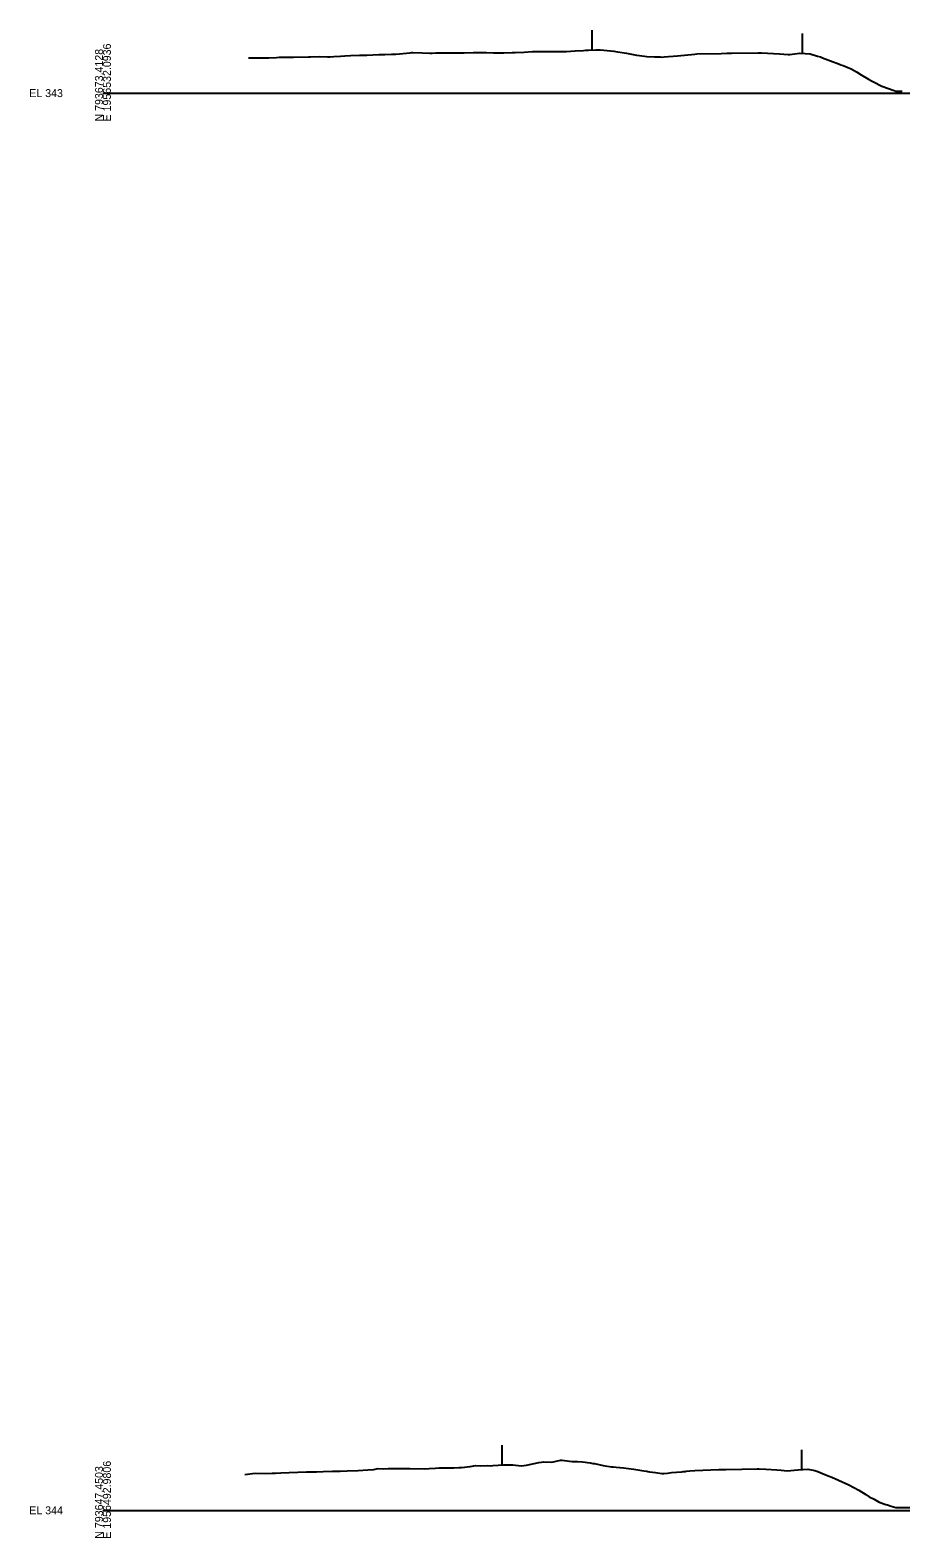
# Model space of a CAD drawing. Extents: x -4026 to 9638, y -10 to 19609.
# Drawn here: x -3026 to -2718, y -10 to 522 of the extents above; entities that cross this region are included whole.
import ezdxf

# ---------------------------------------------------------------- set-up
doc = ezdxf.new("R2010")
doc.units = 0
for name, color, linetype in [('Default', 7, 'Continuous'), ('RD_EX_Fence_Other', 7, 'Continuous'), ('RD_GPK_XS_Cell', 7, 'Continuous'), ('RD_XS_ExGround', 7, 'Continuous')]:
    doc.layers.add(name, color=color, linetype=linetype)

msp = doc.modelspace()

# ---------------------------------------------------------------- linework, layer by layer
at = {"layer": 'RD_EX_Fence_Other'}
for p, q in [((-2827.49, 522.22), (-2827.49, 515.22)), ((-2753.34, 521.04), (-2753.34, 514.04)), ((-2859.28, 23.03), (-2859.28, 16.03)), ((-2753.49, 21.41), (-2753.49, 14.41))]:
    msp.add_line(p, q, dxfattribs=at)
at = {"layer": 'RD_GPK_XS_Cell'}
for p, q in [((-3000, 500), (-2650, 500)), ((-3000, 0), (-2650, 0))]:
    msp.add_line(p, q, dxfattribs=at)
at = {"layer": 'RD_XS_ExGround'}
for points in [[(-2948.67, 512.41), (-2945.47, 512.47), (-2944.79, 512.47), (-2941.46, 512.47), (-2938.77, 512.62), (-2937.86, 512.66), (-2936.49, 512.71), (-2932.76, 512.74), (-2927.5, 512.78), (-2927.04, 512.8), (-2926.74, 512.8), (-2923.44, 512.9), (-2920.72, 512.84), (-2919.84, 512.84), (-2918.52, 512.9), (-2916.23, 513.05), (-2914.7, 513.13), (-2912.63, 513.28), (-2909.54, 513.37), (-2909.02, 513.4), (-2908.68, 513.4), (-2906.94, 513.45), (-2902.66, 513.57), (-2900.56, 513.62), (-2898.21, 513.73), (-2896.64, 513.8), (-2891.58, 514.23), (-2891.01, 514.3), (-2890.62, 514.29), (-2887.4, 514.16), (-2884.61, 514.15), (-2883.8, 514.14), (-2882.59, 514.17), (-2880.19, 514.22), (-2878.59, 514.25), (-2873.61, 514.26), (-2872.57, 514.27), (-2869.38, 514.37), (-2866.55, 514.33), (-2865.78, 514.32), (-2864.63, 514.32), (-2862.17, 514.27), (-2860.53, 514.27), (-2858.57, 514.27), (-2855.65, 514.33), (-2854.51, 514.36), (-2851.36, 514.47), (-2848.49, 514.68), (-2846.66, 514.69), (-2844.16, 514.66), (-2842.47, 514.66), (-2840.55, 514.7), (-2837.68, 514.72), (-2836.95, 514.73), (-2836.46, 514.74), (-2833.34, 514.91), (-2830.44, 515.06), (-2829.74, 515.1), (-2828.7, 515.14), (-2826.14, 515.3), (-2824.42, 515.27), (-2819.72, 514.81), (-2818.4, 514.6), (-2815.32, 514.08), (-2812.38, 513.52), (-2811.72, 513.41), (-2810.74, 513.29), (-2808.12, 512.97), (-2805.43, 512.85), (-2804.72, 512.81), (-2803.37, 512.77), (-2802.89, 512.74), (-2801.99, 512.79), (-2797.31, 513.12), (-2791.22, 513.74), (-2790.51, 513.81), (-2781.89, 514.03), (-2779.85, 514.08), (-2778.26, 514.1), (-2768.86, 514.23), (-2767.6, 514.18), (-2761.27, 513.9), (-2758.21, 513.65), (-2757.66, 513.63), (-2756.84, 513.71), (-2754.06, 514.06), (-2752.19, 514.01), (-2750.46, 513.9), (-2747.86, 513.04), (-2746.85, 512.75), (-2746.17, 512.48), (-2743.25, 511.43), (-2740.16, 510.25), (-2739.64, 510.04), (-2738.88, 509.75), (-2736.04, 508.56), (-2734.14, 507.52), (-2732.44, 506.41), (-2729.9, 504.96), (-2728.83, 504.37), (-2728.12, 503.98), (-2725.23, 502.48), (-2720.79, 500.9), (-2720.22, 500.69), (-2719.34, 500.67), (-2717.96, 500.65)], [(-2949.91, 12.71), (-2946.26, 13.12), (-2942.69, 13.05), (-2940.28, 13.11), (-2939.08, 13.18), (-2937.26, 13.26), (-2934.3, 13.33), (-2928.16, 13.61), (-2924.64, 13.62), (-2922.33, 13.73), (-2919.06, 13.81), (-2917.42, 13.81), (-2916.34, 13.85), (-2913.81, 13.93), (-2909.96, 14.09), (-2906.59, 14.26), (-2904.38, 14.45), (-2902.98, 14.73), (-2900.86, 14.66), (-2899.37, 14.72), (-2898.39, 14.72), (-2895.76, 14.77), (-2892.15, 14.77), (-2891.75, 14.76), (-2886.42, 14.67), (-2884.93, 14.78), (-2882.65, 14.91), (-2881.32, 14.97), (-2880.44, 14.95), (-2876.19, 15.04), (-2874.46, 15.08), (-2873.55, 15.16), (-2870.49, 15.44), (-2868.47, 15.78), (-2866.88, 15.68), (-2864.45, 15.83), (-2863.27, 15.76), (-2862.49, 15.85), (-2858.72, 16.06), (-2856.5, 16.12), (-2855.35, 16.09), (-2852.44, 15.66), (-2850.52, 15.99), (-2846.25, 16.85), (-2845.22, 16.98), (-2844.54, 17.07), (-2841.61, 17.01), (-2838.55, 17.68), (-2838, 17.67), (-2837.15, 17.62), (-2834.39, 17.28), (-2832.57, 17.3), (-2830.77, 17.07), (-2828.05, 16.74), (-2827.16, 16.57), (-2826.58, 16.48), (-2823.55, 15.88), (-2820.6, 15.4), (-2819.94, 15.33), (-2818.95, 15.25), (-2816.33, 14.95), (-2814.62, 14.77), (-2812.72, 14.54), (-2809.85, 14.06), (-2809.11, 13.95), (-2808.1, 13.8), (-2807.79, 13.75), (-2807.16, 13.64), (-2805.08, 13.31), (-2802.83, 12.95), (-2802.1, 13.03), (-2800.76, 13.18), (-2800.06, 13.26), (-2799.34, 13.33), (-2797.67, 13.51), (-2795.7, 13.65), (-2795.26, 13.69), (-2794.59, 13.75), (-2794.25, 13.79), (-2792.87, 13.91), (-2791.11, 14.05), (-2782.74, 14.38), (-2780.23, 14.46), (-2774.61, 14.56), (-2769.19, 14.66), (-2768.41, 14.61), (-2766.09, 14.49), (-2762.18, 14.3), (-2760.76, 14.16), (-2758.57, 13.96), (-2754.78, 14.33), (-2751.35, 14.55), (-2748.79, 14.01), (-2747.74, 13.71), (-2746.14, 13.04), (-2744.13, 12.22), (-2742.81, 11.66), (-2740.52, 10.67), (-2736.82, 9), (-2733.3, 7.12), (-2730.84, 5.56), (-2729.69, 4.82), (-2727.94, 3.93), (-2726.08, 2.89), (-2723.82, 2.09), (-2723.18, 1.94), (-2721.87, 1.49), (-2720.3, 1.01), (-2719.32, 0.98), (-2715.25, 1)]]:
    msp.add_lwpolyline(points, dxfattribs=at)

# ---------------------------------------------------------------- texts
at = {"layer": 'Default'}
for p in [(-3000, 500), (-3000, 0)]:
    msp.add_text('-', height=0.0001, dxfattribs=at).set_placement(p)
at = {"layer": 'RD_GPK_XS_Cell'}
for s, p in [('E 1956532.0936', (-2997.2, 490)), ('N 793673.4128', (-3000, 490)), ('E 1956492.9806', (-2997.2, -10)), ('N 793647.4503', (-3000, -10))]:
    msp.add_text(s, height=2.8, rotation=90, dxfattribs=at).set_placement(p)
for s, p in [('EL 343', (-3026, 498.6)), ('EL 344', (-3026, -1.4))]:
    msp.add_text(s, height=2.8, dxfattribs=at).set_placement(p)

doc.saveas('drawing.dxf')
